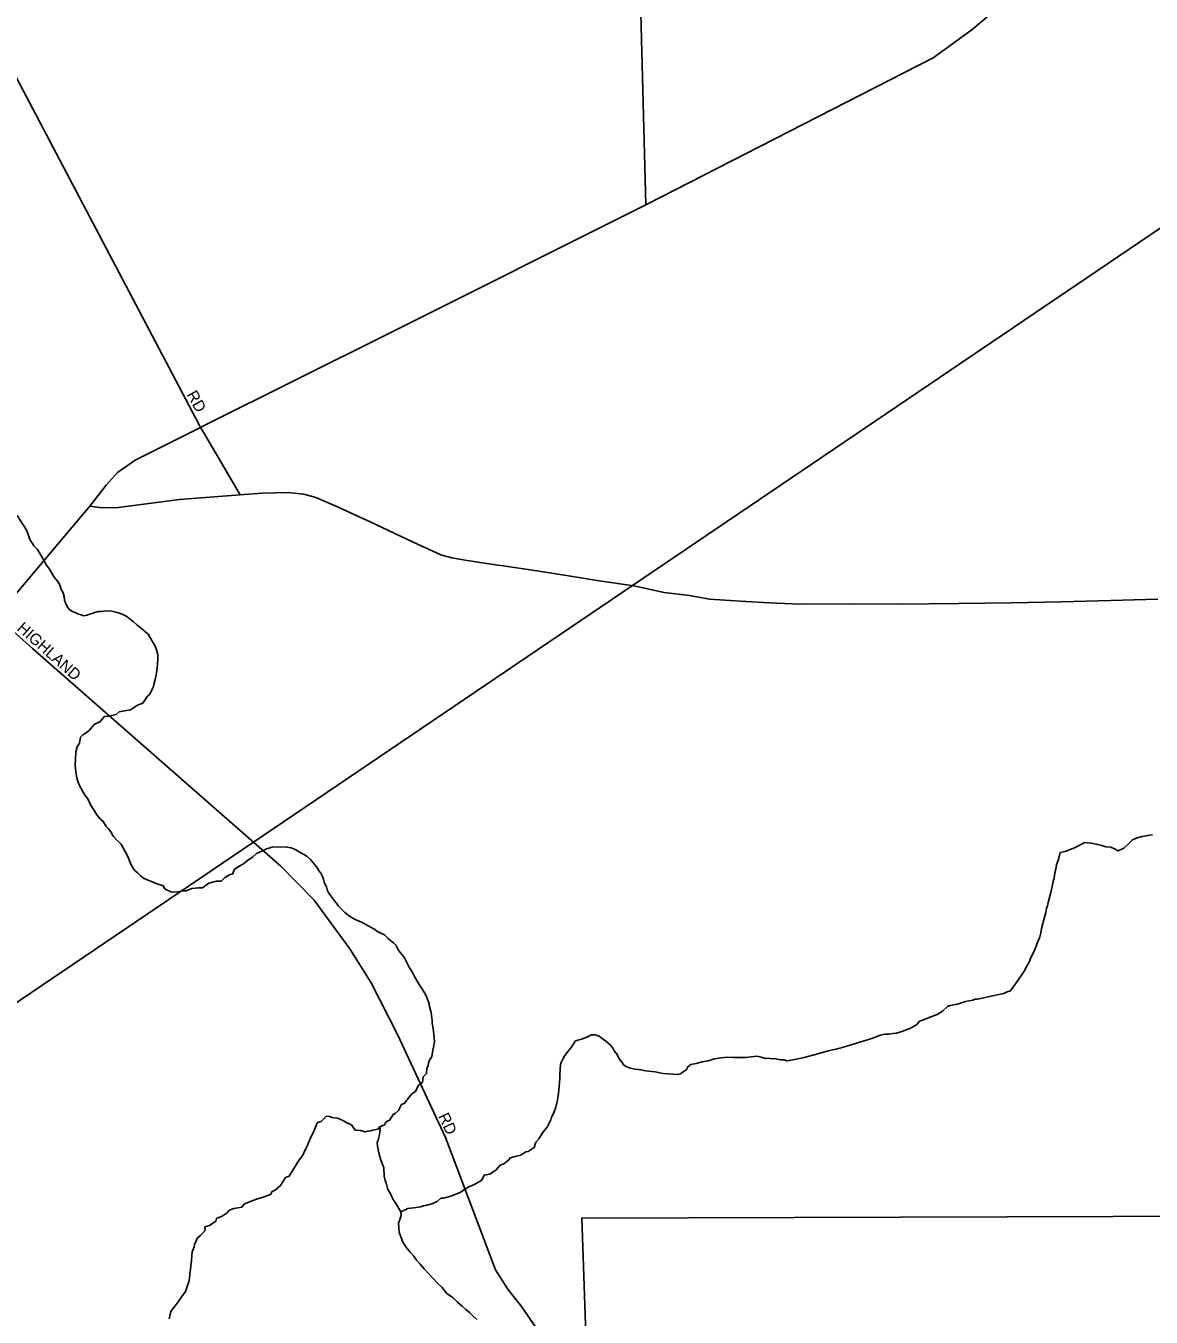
# Model space of a CAD drawing. Extents: x 2139079 to 2262683, y 1235796 to 1334992.
# Drawn here: x 2232304 to 2237265, y 1297941 to 1303635 of the extents above; entities that cross this region are included whole.
import ezdxf

# ---------------------------------------------------------------- set-up
doc = ezdxf.new("R2010")
doc.units = 0
for name, color, linetype in [('GM_X_City_Street', 7, 'Continuous'), ('GM_X_City_Street_Text', 7, 'Continuous'), ('GM_X_Interstate_Route', 7, 'Continuous'), ('GM_X_Minor_River', 7, 'Continuous'), ('GM_X_US_Route', 7, 'Continuous')]:
    doc.layers.add(name, color=color, linetype=linetype)

msp = doc.modelspace()

# ---------------------------------------------------------------- linework, layer by layer
at = {"layer": 'GM_X_City_Street'}
for points in [[(2235037.4, 1302845.4), (2234996.7, 1304364.6)], [(2233088.2, 1301840), (2233073.5, 1301864.9), (2233067.4, 1301875.3), (2232171, 1303576.2), (2232079.2, 1303776.5), (2232018.5, 1303862.8), (2231965.8, 1303917.1), (2231913.1, 1303961.8), (2231842.8, 1304001.7), (2231723.7, 1304043.3), (2231524.1, 1304095.9), (2230915.6, 1304246.1), (2230871.3, 1304269.6)], [(2233249, 1301567.5), (2233088.2, 1301840)], [(2232174.4, 1301030.1), (2232333.7, 1300890.2)], [(2232333.7, 1300890.2), (2233427.8, 1299929.6), (2233574.5, 1299779.9), (2233732.6, 1299565.3), (2233825.7, 1299415.7), (2233941.5, 1299187), (2234153.3, 1298733.5), (2234373.7, 1298149.7), (2234428.1, 1298064.8), (2234470.9, 1298010.6), (2234484, 1297994), (2234501.6, 1297968.6)], [(2234501.6, 1297968.6), (2234607, 1297816.4), (2234737.3, 1297663.1), (2234755.9, 1297637.8), (2234791, 1297589.9)]]:
    msp.add_lwpolyline(points, dxfattribs=at)
at = {"layer": 'GM_X_Interstate_Route'}
msp.add_lwpolyline([(2238501.9, 1298389.4), (2234754.2, 1298378.1), (2234938.8, 1293048)], dxfattribs=at)
msp.add_lwpolyline([(2238501.9, 1298389.4), (2234754.2, 1298378.1), (2234938.8, 1293048)], dxfattribs=at)
at = {"layer": 'GM_X_Minor_River'}
for points in [[(2232266.2, 1301476.3), (2232305.6, 1301414.8), (2232312, 1301396.8), (2232318.4, 1301378.8), (2232324.7, 1301364.9), (2232330.9, 1301355), (2232339.2, 1301343.1), (2232353.6, 1301327.3), (2232364, 1301311.4), (2232374.4, 1301293.5), (2232384.8, 1301275.6), (2232395.2, 1301257.8), (2232407.6, 1301239.9), (2232418, 1301222), (2232426.3, 1301208.1), (2232434.6, 1301196.2), (2232444.9, 1301184.4), (2232453.2, 1301170.5), (2232459.6, 1301150.5), (2232468, 1301134.6), (2232472.3, 1301118.6), (2232474.7, 1301102.5), (2232478.9, 1301090.6), (2232483.1, 1301080.6), (2232489.4, 1301070.7), (2232497.6, 1301060.8), (2232509.8, 1301053), (2232524, 1301047.2), (2232536.1, 1301041.4), (2232548.3, 1301037.7), (2232558.4, 1301033.8), (2232574.4, 1301036.1), (2232584.4, 1301040.4), (2232596.3, 1301044.6), (2232608.3, 1301048.9), (2232624.3, 1301053.2), (2232636.3, 1301053.4), (2232656.3, 1301055.8), (2232682.5, 1301054.3), (2232706.7, 1301048.8), (2232728.9, 1301041.2), (2232749.2, 1301031.5), (2232763.5, 1301019.7), (2232777.8, 1301007.9), (2232792.1, 1300996.2), (2232806.4, 1300984.4), (2232843.2, 1300952.9), (2232849.4, 1300943), (2232855.7, 1300931.1), (2232861.9, 1300919.1), (2232870.3, 1300905.2), (2232876.5, 1300893.3), (2232880.8, 1300879.3), (2232885.2, 1300863.3), (2232885.6, 1300843.2), (2232884, 1300823.1), (2232882.4, 1300803), (2232879, 1300772.8), (2232873.4, 1300752.6), (2232869.7, 1300736.4), (2232866, 1300722.3), (2232860.2, 1300710.1), (2232850.6, 1300687.8), (2232840.7, 1300679.6)], [(2232840.7, 1300679.6), (2232819.3, 1300649), (2232795.4, 1300640.5), (2232765.7, 1300619.8), (2232729.7, 1300613.1), (2232715.6, 1300610.8), (2232701.8, 1300598.5), (2232669.8, 1300591.9), (2232649.8, 1300589.5), (2232630.2, 1300567), (2232604.4, 1300554.4), (2232582.8, 1300527.9), (2232565, 1300515.5), (2232555.1, 1300509.3), (2232545.2, 1300499), (2232539.8, 1300472.8), (2232530, 1300456.5), (2232524.5, 1300434.3), (2232523.1, 1300402.1), (2232521.7, 1300374), (2232524.3, 1300345.9), (2232528.9, 1300317.8), (2232537.4, 1300291.9), (2232547.9, 1300272), (2232556.2, 1300256.1), (2232564.6, 1300242.2), (2232574.9, 1300228.3), (2232583.2, 1300214.4), (2232589.5, 1300200.4), (2232597.8, 1300186.5), (2232608.2, 1300170.6), (2232616.5, 1300156.8), (2232624.7, 1300146.9), (2232633, 1300137), (2232645.2, 1300127.2), (2232657.7, 1300105.3), (2232666, 1300095.4), (2232678.3, 1300081.6), (2232688.7, 1300061.7), (2232705.2, 1300043.9), (2232723.6, 1300026.2), (2232752.8, 1299972.5), (2232759.1, 1299958.5), (2232763.4, 1299944.6), (2232769.6, 1299934.6), (2232775.9, 1299922.7), (2232784.2, 1299910.8), (2232796.4, 1299901), (2232808.8, 1299887.2), (2232823, 1299877.4), (2232839.3, 1299869.7), (2232857.5, 1299862), (2232885.8, 1299850.5), (2232908, 1299844.9), (2232918.4, 1299829), (2232942.7, 1299817.4), (2232956.8, 1299815.7), (2232972.9, 1299816), (2232996.9, 1299820.5), (2233010.9, 1299820.7), (2233034.8, 1299831.2), (2233064.9, 1299833.8), (2233083, 1299834.2), (2233110.6, 1299854.8), (2233144.6, 1299863.5), (2233164.7, 1299863.9), (2233180.4, 1299880.3), (2233204.2, 1299892.8), (2233214.2, 1299895), (2233223.8, 1299917.3), (2233247.6, 1299931.8), (2233263.5, 1299940.2), (2233273.4, 1299948.4), (2233287.2, 1299958.7), (2233303.1, 1299969.1), (2233320.8, 1299985.5), (2233346.7, 1299998.1), (2233364.6, 1300006.4), (2233380.5, 1300010.8), (2233390.5, 1300015), (2233454.8, 1300014.2), (2233472.9, 1300010.6), (2233491.2, 1300002.9), (2233509.4, 1299993.2), (2233525.7, 1299983.4), (2233541.9, 1299973.7), (2233558.3, 1299959.9), (2233570.7, 1299944.1), (2233581, 1299932.2), (2233589.2, 1299920.4), (2233597.5, 1299908.5), (2233603.7, 1299898.5), (2233610, 1299886.6), (2233616.3, 1299872.6), (2233620.7, 1299854.6), (2233629.1, 1299838.7), (2233633.4, 1299820.7), (2233641.8, 1299806.8), (2233652.1, 1299792.9), (2233662.4, 1299779.1), (2233672.7, 1299767.2)], [(2237271, 1300068), (2237251, 1300065.6), (2237225, 1300061.1), (2237203, 1300054.7), (2237183.1, 1300046.2), (2237167.3, 1300031.8), (2237143.7, 1300009.3), (2237119.9, 1299996.8), (2237103.6, 1300006.5), (2237087.4, 1300014.2), (2237065.3, 1300015.8), (2237047.1, 1300021.5), (2237022.8, 1300027), (2237000.7, 1300030.6), (2236984.6, 1300032.3), (2236972.5, 1300034.1), (2236926.8, 1300011.1), (2236885, 1299994.2)], [(2236885, 1299994.2), (2236863, 1299989.8), (2236857.4, 1299965.6), (2236851.8, 1299947.4), (2236848, 1299937.2), (2236846.2, 1299927.1), (2236844.4, 1299917.1), (2236840.7, 1299900.9), (2236839, 1299886.8), (2236835.2, 1299872.7), (2236831.6, 1299856.5), (2236827.9, 1299840.4), (2236822.4, 1299814.1), (2236816.8, 1299791.9), (2236811.2, 1299769.7), (2236807.5, 1299755.6), (2236803.8, 1299743.4), (2236800.1, 1299725.3), (2236794.5, 1299705.1), (2236781.5, 1299654.6), (2236777.8, 1299636.4), (2236774.2, 1299618.2), (2236768.4, 1299604.1), (2236760.8, 1299585.8), (2236753.2, 1299565.6), (2236743.6, 1299543.3), (2236733.9, 1299527), (2236728.2, 1299508.8), (2236716.6, 1299488.5), (2236705, 1299466.2), (2236693.3, 1299449.9), (2236679.7, 1299429.5), (2236666, 1299411.2), (2236658.2, 1299398.9), (2236644.5, 1299380.6), (2236630.5, 1299376.3), (2236614.7, 1299368), (2236578.6, 1299361.2), (2236532.7, 1299350.3), (2236498.7, 1299343.6), (2236488.6, 1299343.4), (2236478.7, 1299339.2), (2236446.7, 1299332.6), (2236410.8, 1299321.8), (2236380.8, 1299315.2), (2236366.8, 1299310.9), (2236345.1, 1299290.4), (2236321.3, 1299275.9), (2236285.5, 1299263.1), (2236261.6, 1299252.6), (2236243.6, 1299246.2), (2236229.9, 1299229.9), (2236204.1, 1299215.3), (2236170.2, 1299202.6), (2236142.3, 1299194), (2236126.3, 1299191.7), (2236110.3, 1299189.4), (2236090.2, 1299189), (2236070.2, 1299184.6), (2236038.3, 1299171.9), (2235922.6, 1299135.5), (2235892.7, 1299126.9), (2235874.7, 1299122.5), (2235840.7, 1299115.8), (2235794.8, 1299102.9), (2235734.9, 1299085.6), (2235692.9, 1299076.8), (2235668.9, 1299072.3), (2235658.8, 1299072.1), (2235646.7, 1299075.9), (2235632.7, 1299075.6), (2235622.6, 1299077.4), (2235604.4, 1299081.1), (2235592.4, 1299080.9), (2235578.3, 1299082.6), (2235566.3, 1299082.4), (2235546.1, 1299088), (2235527.9, 1299091.7), (2235501.9, 1299089.2), (2235475.8, 1299086.6), (2235449.7, 1299086.1), (2235421.6, 1299085.6), (2235395.5, 1299087.1), (2235369.4, 1299084.6), (2235339.4, 1299080), (2235311.5, 1299071.4), (2235285.4, 1299066.9), (2235259.5, 1299060.4), (2235235.5, 1299055.9), (2235221.6, 1299045.6), (2235215.8, 1299033.4), (2235202, 1299023.1), (2235190.1, 1299014.8), (2235180.2, 1299010.6), (2235113.8, 1299015.3), (2235077.5, 1299022.7), (2235035.2, 1299027.9), (2235015.1, 1299031.5), (2235003, 1299033.3), (2234986.9, 1299035), (2234968.7, 1299038.7)], [(2233672.7, 1299767.2), (2233681, 1299755.3), (2233693.3, 1299741.5), (2233709.7, 1299725.7), (2233730.1, 1299710.1), (2233752.5, 1299696.4), (2233772.7, 1299686.8), (2233782.8, 1299682.9), (2233793, 1299679.1), (2233813.3, 1299667.4), (2233823.4, 1299661.6), (2233837.7, 1299653.8), (2233856, 1299640.1), (2233866.1, 1299636.3), (2233884.4, 1299626.6), (2233900.8, 1299610.9), (2233913, 1299601.1), (2233925.3, 1299591.2), (2233935.6, 1299579.4), (2233943.9, 1299563.5), (2233954.3, 1299549.6), (2233964.5, 1299537.7), (2233972.8, 1299525.8), (2233995.8, 1299482.1), (2234006.2, 1299464.2), (2234018.7, 1299440.3), (2234031.2, 1299418.4), (2234043.7, 1299398.6), (2234056.1, 1299378.7), (2234066.6, 1299360.8), (2234075, 1299342.9), (2234081.3, 1299324.9), (2234083.6, 1299310.9), (2234088, 1299294.9), (2234090.2, 1299284.9), (2234094.9, 1299248.8)], [(2234094.9, 1299248.8), (2234095.2, 1299236.8), (2234097.5, 1299222.8), (2234099.7, 1299212.8), (2234102.2, 1299188.7), (2234104.5, 1299174.7), (2234104.9, 1299154.6), (2234101.4, 1299132.4), (2234097.6, 1299118.3), (2234094.2, 1299090.1), (2234082.5, 1299071.8), (2234078.7, 1299061.6), (2234076.9, 1299051.5), (2234071.2, 1299037.4), (2234069.6, 1299015.2), (2234055.9, 1299000.9), (2234052.3, 1298976.7), (2234034.5, 1298964.3), (2234021, 1298935.9), (2234005.2, 1298925.6), (2233971.9, 1298882.7), (2233960, 1298878.4), (2233946.4, 1298852.1), (2233932.6, 1298839.7), (2233922.7, 1298835.5), (2233909.1, 1298811.1), (2233891.3, 1298800.8), (2233885.5, 1298788.6), (2233863.6, 1298780.1), (2233855.8, 1298769.9), (2233833.8, 1298765.5), (2233823.8, 1298763.3), (2233811.8, 1298761), (2233801.8, 1298758.8), (2233779.6, 1298764.4), (2233755.4, 1298766), (2233738.9, 1298789.8), (2233716.6, 1298799.4), (2233706.4, 1298805.2), (2233692.2, 1298813), (2233678, 1298818.7), (2233664, 1298820.5), (2233653.9, 1298822.3), (2233641.8, 1298826.1), (2233629.7, 1298827.8), (2233606.1, 1298803.3), (2233590.1, 1298798.9), (2233576.7, 1298768.5), (2233567, 1298748.2), (2233559.3, 1298732), (2233553.6, 1298719.9), (2233547.8, 1298707.7), (2233544, 1298695.6), (2233538.2, 1298683.4), (2233532.4, 1298673.2), (2233526.7, 1298659.1), (2233516.9, 1298644.8), (2233509.1, 1298634.6), (2233497.4, 1298616.3), (2233464.4, 1298563.4), (2233448.5, 1298557.1), (2233427.1, 1298522.5), (2233403.4, 1298501.9), (2233389.5, 1298495.6), (2233381.7, 1298481.4), (2233345.8, 1298468.6), (2233319.9, 1298462.1), (2233268.1, 1298441), (2233256.3, 1298426.7), (2233220.3, 1298420), (2233200.4, 1298413.6), (2233190.6, 1298401.3), (2233168.8, 1298386.8), (2233144.9, 1298376.3), (2233141.2, 1298364.2), (2233113.4, 1298345.6), (2233093.5, 1298339.2), (2233093.8, 1298323.1), (2233074.2, 1298300.6), (2233060.3, 1298290.3), (2233056.5, 1298280.2), (2233046.9, 1298261.9), (2233045.1, 1298251.8), (2233037.5, 1298229.6), (2233035.8, 1298213.4), (2233034.3, 1298189.3), (2233030.7, 1298169.1), (2233029.1, 1298151), (2233027.4, 1298132.9), (2233025.8, 1298112.8), (2233022.1, 1298096.6), (2233014.5, 1298076.4), (2233006.9, 1298054.1), (2232991.3, 1298031.7), (2232975.7, 1298009.3), (2232962, 1297991), (2232950.3, 1297976.7), (2232942.5, 1297966.5), (2232935.1, 1297934.2)], [(2234968.7, 1299038.7), (2234952.6, 1299044.4), (2234940.4, 1299052.2), (2234932.1, 1299064.1), (2234919.7, 1299079.9), (2234911.3, 1299099.8), (2234896.9, 1299115.6), (2234890.6, 1299129.6), (2234880.3, 1299141.4), (2234870.1, 1299151.3), (2234859.9, 1299159.1), (2234849.7, 1299165), (2234831.3, 1299180.7), (2234813.1, 1299186.4), (2234797.1, 1299186.1), (2234777.2, 1299175.6), (2234757.2, 1299169.2), (2234737.3, 1299162.8), (2234725.3, 1299158.6), (2234709.8, 1299132.1), (2234694.1, 1299113.7), (2234680.4, 1299095.4), (2234670.7, 1299079.1), (2234663, 1299064.9), (2234661.2, 1299054.8), (2234658.1, 1299010.5), (2234658.4, 1298994.5), (2234656.8, 1298976.3), (2234655.1, 1298958.2), (2234653.5, 1298942.1), (2234651.7, 1298928), (2234649.9, 1298917.9), (2234646.4, 1298891.7), (2234640.9, 1298867.5), (2234633.3, 1298847.3), (2234627.6, 1298833.1), (2234621.8, 1298822.9), (2234618, 1298810.8), (2234610.2, 1298796.6), (2234602.6, 1298778.3), (2234592.8, 1298768.1), (2234581, 1298753.8), (2234575.2, 1298743.6), (2234565.5, 1298727.4), (2234551.7, 1298713), (2234544.2, 1298688.8), (2234518.4, 1298672.2), (2234508.4, 1298670), (2234486.6, 1298655.5), (2234460.6, 1298649), (2234438.7, 1298644.5), (2234432.8, 1298634.4), (2234411.1, 1298617.9), (2234395.1, 1298611.5), (2234377.5, 1298591.1), (2234349.8, 1298572.5), (2234323.8, 1298567.9), (2234314.2, 1298545.7), (2234288.4, 1298531.1), (2234268.5, 1298520.6), (2234254.5, 1298516.4), (2234218.9, 1298491.6), (2234177.1, 1298474.7), (2234145.1, 1298466), (2234133.1, 1298465.8), (2234117.3, 1298451.4), (2234093.4, 1298440.9), (2234071.5, 1298434.4), (2234057.4, 1298432.2), (2234043.5, 1298427.9), (2234013.5, 1298423.3), (2233987.4, 1298420.8)], [(2233863.6, 1298780.1), (2233865.7, 1298772.1), (2233862.3, 1298745.9), (2233856.7, 1298721.7), (2233852.9, 1298711.6), (2233853.3, 1298695.5), (2233859.9, 1298665.5), (2233868.6, 1298633.5), (2233877.1, 1298611.6), (2233881.3, 1298599.6), (2233884.1, 1298563.5), (2233888.5, 1298543.4), (2233892.7, 1298533.5), (2233899.4, 1298503.5), (2233909.7, 1298487.6), (2233913.9, 1298477.6), (2233924.4, 1298457.7), (2233932.7, 1298445.8), (2233957.6, 1298406.1)], [(2233987.4, 1298420.8), (2233957.6, 1298406.1), (2233957.9, 1298390.1), (2233950.3, 1298367.8), (2233946.6, 1298355.6), (2233949.4, 1298315.5), (2233966.4, 1298271.6), (2233982.9, 1298245.8), (2233999.4, 1298226.1), (2234013.8, 1298210.2), (2234026.2, 1298192.4), (2234042.6, 1298174.6), (2234059.1, 1298154.8), (2234077.6, 1298135.1), (2234098.1, 1298113.4), (2234118.6, 1298091.7), (2234139.1, 1298072), (2234159.7, 1298046.3), (2234188.2, 1298026.7), (2234206.7, 1298007), (2234227.2, 1297989.3), (2234243.5, 1297975.5), (2234259.8, 1297961.8), (2234276.2, 1297946), (2234292.6, 1297930.3)]]:
    msp.add_lwpolyline(points, dxfattribs=at)
at = {"layer": 'GM_X_US_Route'}
msp.add_lwpolyline([(2202867.6, 1295541.4), (2210353.6, 1284489.3), (2249318.3, 1310881.6), (2241832.3, 1321933.6)], close=True, dxfattribs=at)
for points in [[(2233900.4, 1302277.8), (2235037.4, 1302845.4), (2236303.7, 1303494.1), (2236383.4, 1303550.9), (2236475.1, 1303619.8), (2236614.4, 1303735.2)], [(2232585.7, 1301517.7), (2232657.6, 1301609.4), (2232708, 1301665.8), (2232785.9, 1301719.8), (2233073.5, 1301864.9), (2233090.1, 1301873.3), (2233900.4, 1302277.8)], [(2233264.4, 1301568.6), (2233349.2, 1301574.3), (2233459.5, 1301577.2), (2233529.7, 1301569.7), (2233581.9, 1301556), (2233664.4, 1301520.5), (2233821.4, 1301447.5), (2234010.6, 1301358.7), (2234133.4, 1301303.4), (2234181.6, 1301289.8), (2234249.8, 1301278.2), (2234384.3, 1301257.1), (2234409.4, 1301253.6)], [(2232585.7, 1301517.7), (2232630, 1301511.1), (2232700.8, 1301510.5), (2232981.4, 1301546.5), (2233249, 1301567.5), (2233264.4, 1301568.6)], [(2229183, 1297752.5), (2229251.9, 1297820.1), (2229410.7, 1297992.1), (2229521.9, 1298111.3), (2229670.9, 1298270.9), (2229823.9, 1298428.5), (2230178.2, 1298753.5), (2231308.8, 1299946.9), (2232174.4, 1301030.1), (2232585.7, 1301517.7)], [(2234409.4, 1301253.6), (2234438.1, 1301249.6), (2234518.8, 1301238.1), (2234687.4, 1301211.3), (2234831.9, 1301188.3), (2234984.5, 1301165.4), (2235117.1, 1301136.3), (2235229.4, 1301123.1), (2235317.8, 1301107.7), (2235385.9, 1301102.2), (2235478.2, 1301096.9), (2235582.5, 1301091.7), (2235716.9, 1301084.6), (2235947.4, 1301086.4), (2236151.9, 1301085.9), (2236416.5, 1301087.9), (2236647, 1301091.6), (2236869.4, 1301095.3), (2237085.9, 1301101), (2237294.3, 1301106.6)]]:
    msp.add_lwpolyline(points, dxfattribs=at)

# ---------------------------------------------------------------- texts
at = {"layer": 'GM_X_City_Street_Text'}
for s, rotation, p in [('RD', 299.3565, (2233011.1, 1302009.6)), ('HIGHLAND', 318.3667, (2232261.2, 1300973.7)), ('RD', 295.1968, (2234120.2, 1298827.8))]:
    msp.add_text(s, height=50, rotation=rotation, dxfattribs=at).set_placement(p)

doc.saveas('drawing.dxf')
